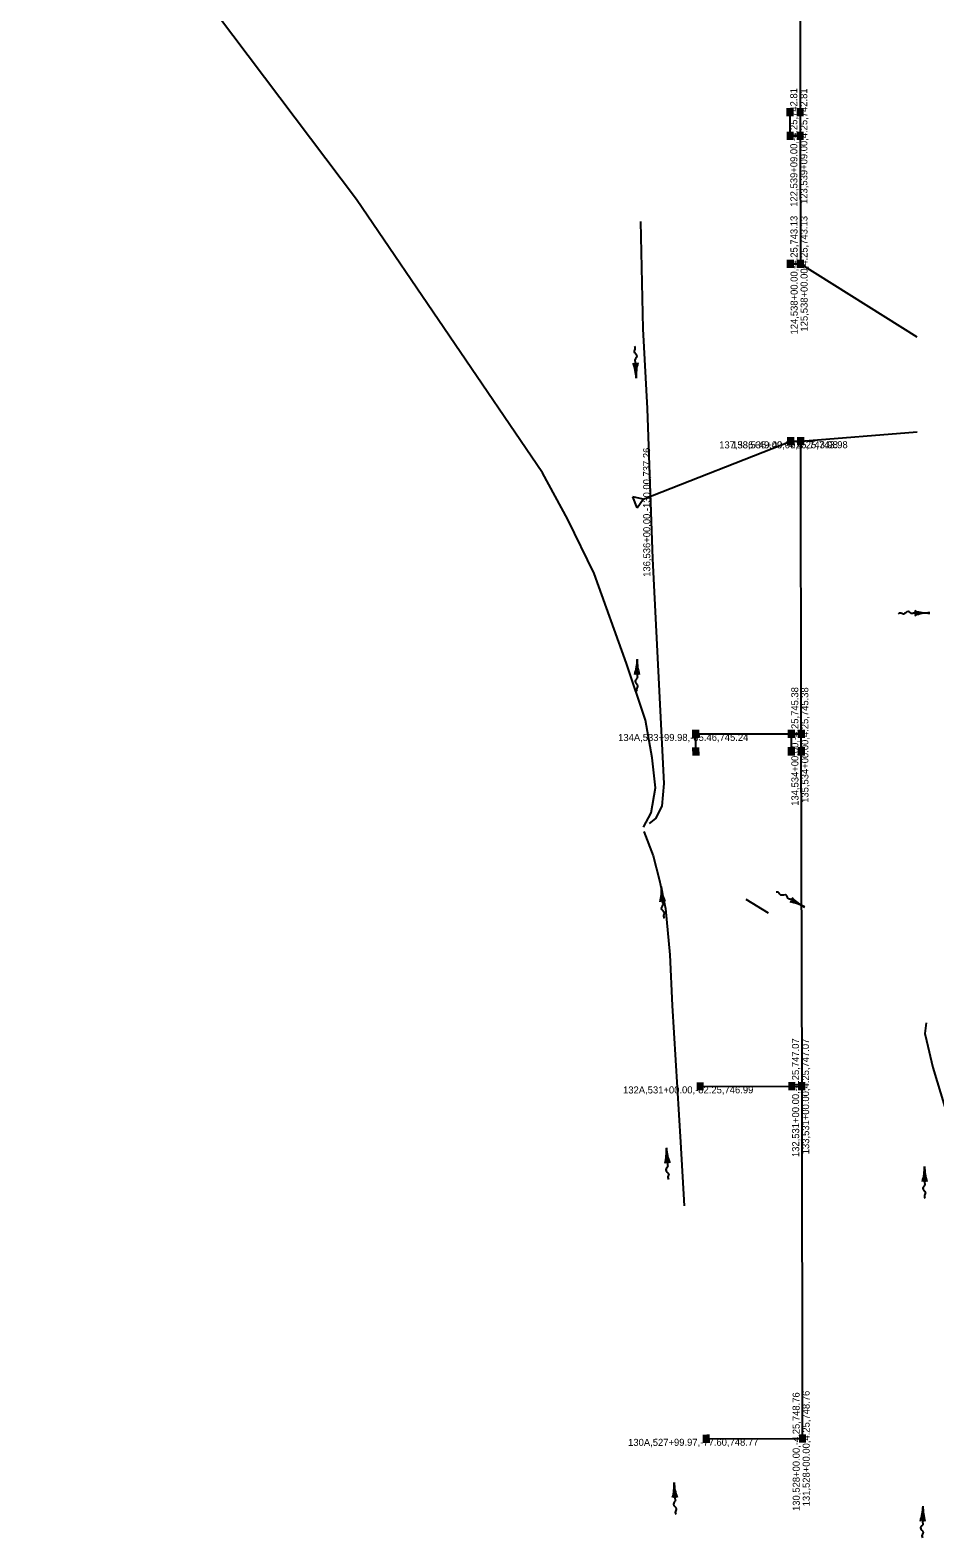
# Model space of a CAD drawing. Extents: x 593481 to 595859, y 150220 to 157407.
# Drawn here: x 593709 to 594479, y 151991 to 153274 of the extents above; entities that cross this region are included whole.
import ezdxf

# ---------------------------------------------------------------- set-up
doc = ezdxf.new("R2010")
doc.units = 0
for name, color, linetype in [('E_PROF_GridMin', 7, 'Continuous'), ('P_ALI_20_Tic', 7, 'Continuous'), ('P_ALI_50_Equation', 7, 'Continuous'), ('P_DRN_SS_UG', 7, 'Continuous'), ('P_RDWY_C_and_G_H', 7, 'Continuous')]:
    doc.layers.add(name, color=color, linetype=linetype)

msp = doc.modelspace()

# ---------------------------------------------------------------- linework, layer by layer
at = {"layer": 'E_PROF_GridMin'}
for p, q in [((594364.3, 153455.3), (594364.8, 153184.2)), ((594356.3, 153184.2), (594356.3, 153204.2)), ((594356.3, 153184.2), (594364.8, 153184.2)), ((594364.8, 153184.2), (594365, 153075.2)), ((594356.5, 153075.2), (594365, 153075.2)), ((594365, 153075.2), (594463.9, 153013.1)), ((594365.3, 152924.3), (594464.3, 152932.3)), ((594231.1, 152875), (594356.8, 152924.2)), ((594356.8, 152924.2), (594365.3, 152924.3)), ((594365.7, 152675.3), (594365.3, 152924.3)), ((594276, 152675.1), (594357.2, 152675.2)), ((594276, 152660.1), (594276, 152675.1)), ((594357.2, 152675.2), (594365.7, 152675.3)), ((594357.3, 152660.2), (594357.2, 152675.2)), ((594366.3, 152375.3), (594365.7, 152675.3)), ((594337.9, 152522.4), (594318.8, 152534.1)), ((594279.8, 152375.1), (594357.8, 152375.2)), ((594357.8, 152375.2), (594366.3, 152375.3)), ((594366.8, 152075.3), (594366.3, 152375.3)), ((594285, 152075.1), (594358.3, 152075.2)), ((594358.3, 152075.2), (594366.8, 152075.3))]:
    msp.add_line(p, q, dxfattribs=at)
for points in [[(594231.3, 152595.8), (594238, 152608), (594241.5, 152629.1), (594238.7, 152654.6), (594233.1, 152686.7), (594216.9, 152735.1), (594189.3, 152811.5), (594166.9, 152857.5), (594145.5, 152897.2), (593987.3, 153130.1), (593816.8, 153356.3), (593736.8, 153457), (593709.5, 153500.1)], [(594236.5, 152598.7), (594241.9, 152603), (594247.3, 152613.7), (594249, 152632.8), (594239.2, 152824), (594234.7, 152952), (594231.2, 153020), (594229, 153111.2)], [(594231.7, 152592), (594239.5, 152571.2), (594244.9, 152550.4), (594250.2, 152526.5), (594253.7, 152487.1), (594255.7, 152444), (594262.9, 152327.7), (594266.1, 152273.5)], [(594472, 152429.1), (594470.8, 152420.2), (594472.1, 152414), (594477.6, 152391), (594487.9, 152357.3), (594493.5, 152314.7), (594492.6, 152281.8), (594493.7, 152244.4)]]:
    msp.add_lwpolyline(points, dxfattribs=at)
at = {"layer": 'P_ALI_20_Tic'}
for p, q in [((594225.2, 152978), (594224.6, 152992.1)), ((594475, 152778), (594460.9, 152777.8)), ((594226.1, 152738.6), (594225.9, 152724.4)), ((594246.5, 152545.1), (594247.7, 152531.1)), ((594368.3, 152527.8), (594355.9, 152534.5)), ((594250.9, 152322.6), (594251.7, 152308.5)), ((594470.5, 152306.9), (594470.6, 152292.8)), ((594257.4, 152037.9), (594258.2, 152023.8)), ((594469.2, 152017.8), (594468.9, 152003.6))]:
    msp.add_line(p, q, dxfattribs=at)
for points in [[(594222.6, 152990.7), (594224.8, 152987.6), (594226.6, 152990.9)], [(594462.2, 152775.8), (594465.4, 152777.9), (594462.2, 152779.8)], [(594227.9, 152725.7), (594225.9, 152729), (594223.9, 152725.8)], [(594249.6, 152532.6), (594247.3, 152535.6), (594245.6, 152532.2)], [(594356.1, 152532.1), (594359.9, 152532.3), (594358, 152535.6)], [(594253.7, 152310), (594251.5, 152313), (594249.7, 152309.7)], [(594472.6, 152294.1), (594470.6, 152297.3), (594468.6, 152294.1)], [(594260.1, 152025.2), (594257.9, 152028.3), (594256.1, 152025)], [(594470.9, 152004.9), (594469, 152008.2), (594466.9, 152005)]]:
    msp.add_lwpolyline(points, dxfattribs=at)
for centre, start, end in [((594183.2, 152976.2), 2.4314, 20.1937), ((594267.1, 152979.8), 164.6691, 182.4314), ((594474.4, 152820), 253.0426, 270.805), ((594475.6, 152736.1), 90.805, 108.5673), ((594184.1, 152739.1), 341.4611, 359.2234), ((594268, 152738), 179.2234, 196.9857), ((594204.7, 152541.4), 347.3129, 5.0752), ((594288.3, 152548.8), 185.0752, 202.8376), ((594348.4, 152490.8), 61.6992, 79.4616), ((594388.2, 152564.7), 223.9369, 241.6992), ((594209, 152320), 345.7579, 3.5203), ((594292.8, 152325.2), 183.5203, 201.2826), ((594428.6, 152306.6), 342.6828, 0.4452), ((594512.5, 152307.2), 180.4452, 198.2075), ((594215.5, 152035.7), 345.2441, 3.0064), ((594299.3, 152040.1), 183.0064, 200.7687), ((594427.3, 152018.7), 340.9517, 358.714), ((594511.2, 152016.8), 178.714, 196.4764)]:
    msp.add_arc(centre, 42, start, end, dxfattribs=at)
for points in [[(594224.6, 152992.1), (594224.2, 152992.9), (594225.9, 152996.6), (594223.6, 153000.4), (594224.4, 153003.3), (594223.7, 153005)], [(594460.9, 152777.8), (594460.1, 152777.5), (594456.5, 152779.3), (594452.6, 152777.1), (594449.7, 152778), (594448, 152777.3)], [(594225.9, 152724.4), (594226.2, 152723.6), (594224.3, 152720), (594226.4, 152716.1), (594225.4, 152713.3), (594226, 152711.5)], [(594355.9, 152534.5), (594355, 152534.6), (594352.8, 152537.9), (594348.3, 152537.9), (594346.2, 152540), (594344.4, 152540.3)], [(594247.7, 152531.1), (594248.1, 152530.3), (594246.5, 152526.5), (594249.1, 152522.8), (594248.4, 152519.9), (594249.2, 152518.3)], [(594251.7, 152308.5), (594252.1, 152307.7), (594250.4, 152304), (594252.9, 152300.2), (594252.1, 152297.4), (594252.8, 152295.7)], [(594470.6, 152292.8), (594470.9, 152292), (594469.1, 152288.4), (594471.3, 152284.5), (594470.4, 152281.6), (594471, 152279.9)], [(594258.2, 152023.8), (594258.5, 152023), (594256.8, 152019.3), (594259.2, 152015.5), (594258.4, 152012.6), (594259.1, 152010.9)], [(594468.9, 152003.6), (594469.2, 152002.8), (594467.2, 151999.3), (594469.3, 151995.3), (594468.3, 151992.5), (594468.9, 151990.8)]]:
    msp.add_spline(points, degree=3, dxfattribs=at)
at = {"layer": 'P_DRN_SS_UG'}
for p, q in [((594354, 153200.8), (594354, 153207.7)), ((594354.9, 153200.8), (594354.9, 153207.7)), ((594355.8, 153200.8), (594355.8, 153207.7)), ((594356.7, 153200.8), (594356.7, 153207.7)), ((594357.6, 153200.8), (594357.6, 153207.7)), ((594358.5, 153200.8), (594358.5, 153207.7)), ((594362.6, 153200.8), (594362.6, 153207.7)), ((594363.5, 153200.8), (594363.5, 153207.7)), ((594364.4, 153200.8), (594364.4, 153207.7)), ((594365.3, 153200.8), (594365.3, 153207.7)), ((594366.2, 153200.8), (594366.2, 153207.7)), ((594367.1, 153200.8), (594367.1, 153207.7)), ((594354.1, 153180.8), (594354.1, 153187.7)), ((594355, 153180.8), (594355, 153187.7)), ((594355.9, 153180.8), (594355.9, 153187.7)), ((594356.8, 153180.8), (594356.8, 153187.7)), ((594357.7, 153180.8), (594357.7, 153187.7)), ((594358.6, 153180.8), (594358.6, 153187.7)), ((594362.6, 153180.8), (594362.6, 153187.7)), ((594363.5, 153180.8), (594363.5, 153187.7)), ((594364.4, 153180.8), (594364.4, 153187.7)), ((594365.3, 153180.8), (594365.3, 153187.7)), ((594366.2, 153180.8), (594366.2, 153187.7)), ((594367.1, 153180.8), (594367.1, 153187.7)), ((594354.3, 153071.8), (594354.3, 153078.7)), ((594355.2, 153071.8), (594355.2, 153078.7)), ((594356.1, 153071.8), (594356.1, 153078.7)), ((594357, 153071.8), (594357, 153078.7)), ((594357.9, 153071.8), (594357.9, 153078.7)), ((594358.8, 153071.8), (594358.8, 153078.7)), ((594362.8, 153071.8), (594362.8, 153078.7)), ((594363.7, 153071.8), (594363.7, 153078.7)), ((594364.6, 153071.8), (594364.6, 153078.7)), ((594365.5, 153071.8), (594365.5, 153078.7)), ((594366.4, 153071.8), (594366.4, 153078.7)), ((594367.3, 153071.8), (594367.3, 153078.7)), ((594354.5, 152920.8), (594354.5, 152927.7)), ((594355.4, 152920.8), (594355.4, 152927.7)), ((594356.3, 152920.8), (594356.3, 152927.7)), ((594357.2, 152920.8), (594357.2, 152927.7)), ((594358.1, 152920.8), (594358.1, 152927.7)), ((594359, 152920.8), (594359, 152927.7)), ((594363, 152920.8), (594363, 152927.7)), ((594363.9, 152920.8), (594363.9, 152927.7)), ((594364.8, 152920.8), (594364.8, 152927.7)), ((594365.7, 152920.8), (594365.7, 152927.7)), ((594366.6, 152920.8), (594366.6, 152927.7)), ((594367.5, 152920.8), (594367.5, 152927.7)), ((594273.8, 152671.6), (594273.7, 152678.5)), ((594274.7, 152671.6), (594274.6, 152678.5)), ((594275.6, 152671.6), (594275.5, 152678.5)), ((594276.5, 152671.6), (594276.4, 152678.5)), ((594277.4, 152671.7), (594277.3, 152678.5)), ((594278.3, 152671.7), (594278.2, 152678.6)), ((594355, 152671.8), (594355, 152678.7)), ((594355.9, 152671.8), (594355.9, 152678.7)), ((594356.8, 152671.8), (594356.8, 152678.7)), ((594357.7, 152671.8), (594357.7, 152678.7)), ((594358.6, 152671.8), (594358.6, 152678.7)), ((594359.5, 152671.8), (594359.5, 152678.7)), ((594363.5, 152671.8), (594363.5, 152678.7)), ((594364.4, 152671.8), (594364.4, 152678.7)), ((594365.3, 152671.8), (594365.3, 152678.7)), ((594366.2, 152671.8), (594366.2, 152678.7)), ((594367.1, 152671.8), (594367.1, 152678.7)), ((594368, 152671.8), (594368, 152678.7)), ((594273.9, 152656.6), (594273.7, 152663.5)), ((594274.8, 152656.6), (594274.6, 152663.5)), ((594275.7, 152656.6), (594275.5, 152663.5)), ((594276.6, 152656.7), (594276.4, 152663.5)), ((594277.5, 152656.7), (594277.3, 152663.6)), ((594278.4, 152656.7), (594278.2, 152663.6)), ((594355, 152656.8), (594355, 152663.7)), ((594355.9, 152656.8), (594355.9, 152663.7)), ((594356.8, 152656.8), (594356.8, 152663.7)), ((594357.7, 152656.8), (594357.7, 152663.7)), ((594358.6, 152656.8), (594358.6, 152663.7)), ((594359.5, 152656.8), (594359.5, 152663.7)), ((594363.5, 152656.8), (594363.5, 152663.7)), ((594364.4, 152656.8), (594364.4, 152663.7)), ((594365.3, 152656.8), (594365.3, 152663.7)), ((594366.2, 152656.8), (594366.2, 152663.7)), ((594367.1, 152656.8), (594367.1, 152663.7)), ((594368, 152656.8), (594368, 152663.7)), ((594277.5, 152371.7), (594277.5, 152378.5)), ((594278.4, 152371.7), (594278.4, 152378.5)), ((594279.3, 152371.7), (594279.3, 152378.5)), ((594280.2, 152371.7), (594280.2, 152378.5)), ((594281.1, 152371.7), (594281.1, 152378.5)), ((594282, 152371.7), (594282, 152378.5)), ((594355.5, 152371.8), (594355.5, 152378.7)), ((594356.4, 152371.8), (594356.4, 152378.7)), ((594357.3, 152371.8), (594357.3, 152378.7)), ((594358.2, 152371.8), (594358.2, 152378.7)), ((594359.1, 152371.8), (594359.1, 152378.7)), ((594360, 152371.8), (594360, 152378.7)), ((594364, 152371.8), (594364, 152378.7)), ((594364.9, 152371.8), (594364.9, 152378.7)), ((594365.8, 152371.8), (594365.8, 152378.7)), ((594366.7, 152371.8), (594366.7, 152378.7)), ((594367.6, 152371.8), (594367.6, 152378.7)), ((594368.5, 152371.8), (594368.5, 152378.7)), ((594282.8, 152071.6), (594282.6, 152078.4)), ((594283.7, 152071.6), (594283.5, 152078.5)), ((594284.6, 152071.6), (594284.4, 152078.5)), ((594285.5, 152071.7), (594285.3, 152078.5)), ((594286.4, 152071.7), (594286.2, 152078.6)), ((594287.3, 152071.7), (594287.1, 152078.6)), ((594364.6, 152071.8), (594364.6, 152078.7)), ((594365.5, 152071.8), (594365.5, 152078.7)), ((594366.4, 152071.8), (594366.4, 152078.7)), ((594367.3, 152071.8), (594367.3, 152078.7)), ((594368.2, 152071.8), (594368.2, 152078.7)), ((594369.1, 152071.8), (594369.1, 152078.7))]:
    msp.add_line(p, q, dxfattribs=at)
for points in [[(594357.3, 153203.2), (594357.3, 153205.2), (594355.3, 153205.2), (594355.3, 153203.2)], [(594365.8, 153203.3), (594365.8, 153205.3), (594363.8, 153205.3), (594363.8, 153203.3)], [(594357.3, 153183.2), (594357.3, 153185.2), (594355.3, 153185.2), (594355.3, 153183.2)], [(594365.8, 153183.3), (594365.8, 153185.3), (594363.8, 153185.2), (594363.8, 153183.2)], [(594357.5, 153074.2), (594357.5, 153076.2), (594355.5, 153076.2), (594355.5, 153074.2)], [(594366, 153074.3), (594366, 153076.3), (594364, 153076.2), (594364, 153074.2)], [(594357.8, 152923.2), (594357.8, 152925.2), (594355.8, 152925.2), (594355.8, 152923.2)], [(594366.3, 152923.3), (594366.3, 152925.3), (594364.3, 152925.2), (594364.3, 152923.2)], [(594277, 152674.1), (594277, 152676.1), (594275, 152676), (594275, 152674)], [(594358.2, 152674.2), (594358.2, 152676.2), (594356.2, 152676.2), (594356.2, 152674.2)], [(594366.7, 152674.3), (594366.7, 152676.3), (594364.7, 152676.2), (594364.7, 152674.2)], [(594277.1, 152659.1), (594277, 152661.1), (594275, 152661.1), (594275.1, 152659.1)], [(594358.3, 152659.2), (594358.3, 152661.2), (594356.3, 152661.2), (594356.3, 152659.2)], [(594366.8, 152659.3), (594366.8, 152661.3), (594364.8, 152661.3), (594364.8, 152659.3)], [(594280.8, 152374.1), (594280.8, 152376.1), (594278.8, 152376.1), (594278.8, 152374.1)], [(594358.8, 152374.2), (594358.8, 152376.2), (594356.8, 152376.2), (594356.8, 152374.2)], [(594367.3, 152374.3), (594367.3, 152376.3), (594365.3, 152376.2), (594365.3, 152374.2)], [(594286, 152074.1), (594285.9, 152076.1), (594283.9, 152076), (594284, 152074)], [(594367.8, 152074.3), (594367.8, 152076.3), (594365.8, 152076.2), (594365.8, 152074.2)]]:
    msp.add_lwpolyline(points, close=True, dxfattribs=at)
at = {"layer": 'P_RDWY_C_and_G_H'}
for p, q in [((594231.1, 152875), (594222.3, 152876.9)), ((594226, 152867.6), (594222.3, 152876.9)), ((594226, 152867.6), (594231.1, 152875))]:
    msp.add_line(p, q, dxfattribs=at)

# ---------------------------------------------------------------- texts
at = {"layer": 'P_ALI_50_Equation'}
for s, rotation, p in [('122,539+09.00,-4.25,742.81', 90.103, (594362.4, 153123.8)), ('123,539+09.00,4.25,742.81', 90.103, (594370.9, 153126.2)), ('124,538+00.00,-4.25,743.13', 90.103, (594362.6, 153015.1)), ('125,538+00.00,4.25,743.13', 90.103, (594371.1, 153017.6)), ('136,536+00.00,-130.00,737.26', 90.103, (594237.2, 152808.8)), ('137,536+49.00,-4.25,743.98', 0.103, (594295.8, 152918.1)), ('138,536+49.00,4.25,743.98', 0.103, (594306.8, 152918.1)), ('134,534+00.00,-4.25,745.38', 90.103, (594363.3, 152613.9)), ('135,534+00.00,4.25,745.38', 90.103, (594371.8, 152616.4)), ('134A,533+99.98,-85.46,745.24', 0.103, (594209.8, 152669)), ('132,531+00.00,-4.25,747.07', 90.103, (594363.9, 152314.9)), ('133,531+00.00,4.25,747.07', 90.103, (594372.4, 152317.3)), ('132A,531+00.00,-82.25,746.99', 0.103, (594214, 152369)), ('130,528+00.00,-4.25,748.76', 90.103, (594364.4, 152013.6)), ('131,528+00.00,4.25,748.76', 90.103, (594372.9, 152017.6)), ('130A,527+99.97,-77.60,748.77', 0.103, (594218.3, 152069))]:
    msp.add_text(s, height=6, rotation=rotation, dxfattribs=at).set_placement(p)

doc.saveas('drawing.dxf')
